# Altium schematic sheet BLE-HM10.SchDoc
size A4
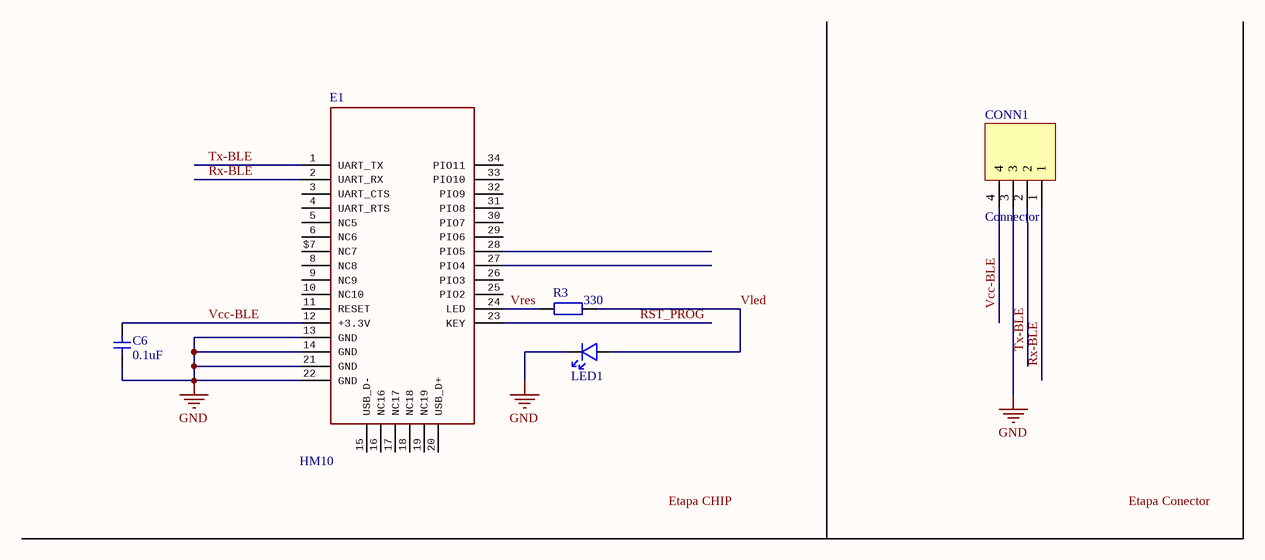
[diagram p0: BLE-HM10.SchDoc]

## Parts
C6  value 0.1uF  [C1206-1.25]  (hidden comment: C2)
CONN1  Connector  [1x4x2.54 Pin Header TH V]
E1  value HM10  [26.9X13X2.2_BOARD]  (hidden comment: HM Bluetooth module use TI CC2540 or CC2541, Master and slave roles in one, transmission version and remote control version and PIO state acquisition functions in one, Support the AT command modify module parameters, Convenient and flexible.)
LED1  LED  [SMT1206-LED]  (value not drawn)
R3  value 330  [R1206-0.55]  (hidden comment: R)

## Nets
GND: C6.1 CONN1.3 E1.13(GND) E1.14(GND) E1.21(GND) E1.22(GND) LED1.2
RST_PROG: E1.23(KEY)
Rx-BLE: CONN1.1 E1.2(UART_RX)
Tx-BLE: CONN1.2 E1.1(UART_TX)
Vcc-BLE: C6.2 CONN1.4 E1.12(+3.3V)
Vled: LED1.1 R3.2
Vres: E1.24(LED) R3.1

Not connected (* = marked no-connect by the designer): E1 3(UART_CTS) 4(UART_RTS) 5(NC5) 6(NC6) 8(NC8) 9(NC9) 10(NC10) 11(RESET) 15(USB_D-) 16(NC16) 17(NC17) 18(NC18) 19(NC19) 20(USB_D+) 25(PIO2) 26(PIO3) 27(PIO4) 28(PIO5) 29(PIO6) 30(PIO7) 31(PIO8) 32(PIO9) 33(PIO10) 34(PIO11) $7(NC7)

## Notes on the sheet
- Labels drawn without touching a wire or pin: Etapa CHIP, Etapa Conector

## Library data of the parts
C6 = C: Capacitor, generic
CONN1 = Header 1x4: Header
E1 = HM-10-BOARD: HM10 BLE
LED1 = LED: *
R3 = R: Resistor, generic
